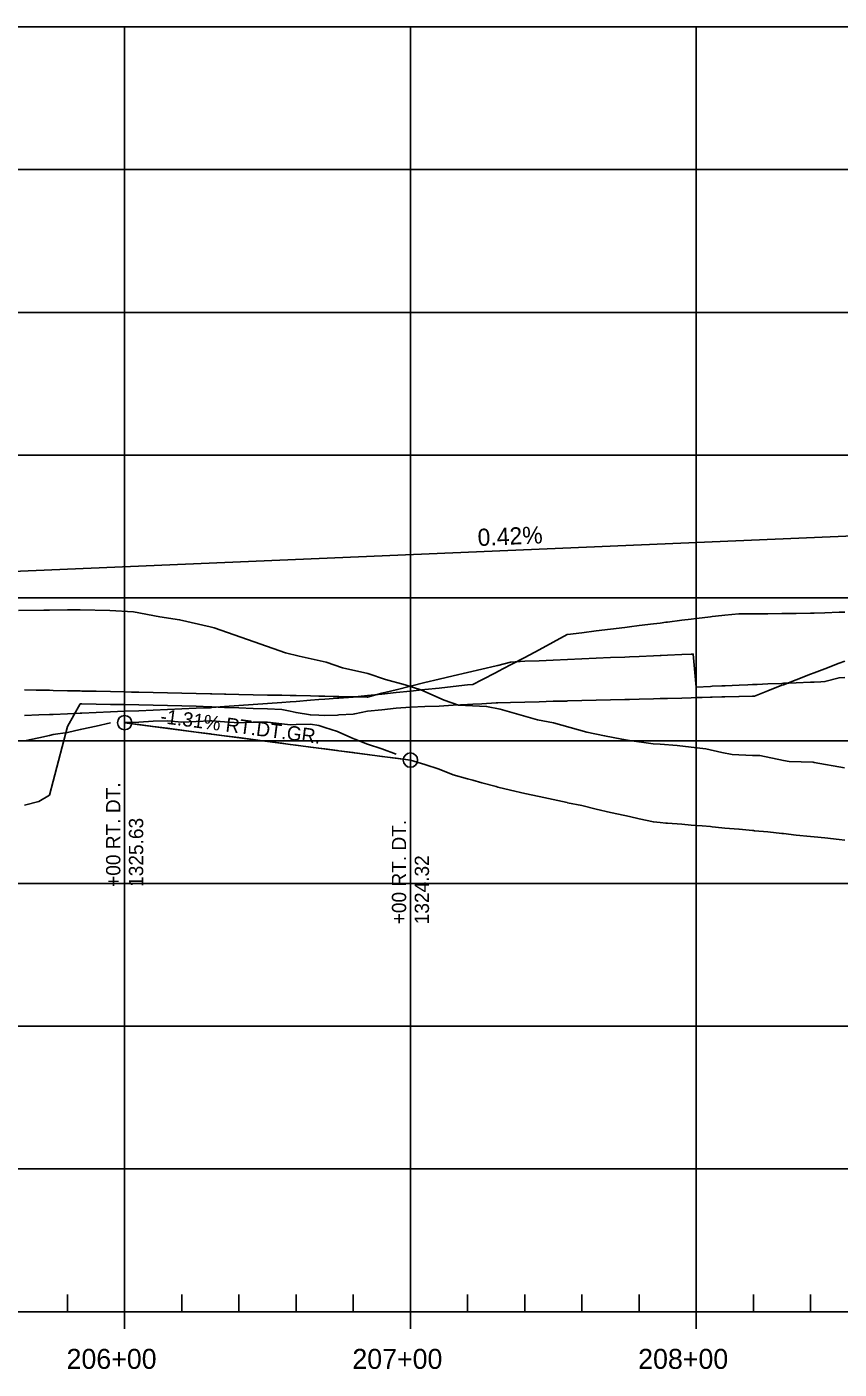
# Model space of a CAD drawing. Extents: x 1371206 to 1374178, y 379328 to 381511.
# Drawn here: x 1371810.4 to 1372094.6, y 379328.3 to 379798.4 of the extents above; entities that cross this region are included whole.
import ezdxf

# ---------------------------------------------------------------- set-up
doc = ezdxf.new("R2010")
doc.units = 0
for name, color, linetype in [('30', 7, 'Continuous'), ('37', 7, 'Continuous'), ('R_Exist Surface', 7, 'Continuous'), ('R_Profile Work Left', 7, 'Continuous'), ('R_Profile Work Right', 7, 'Continuous'), ('R_Vert Alg', 7, 'Continuous'), ('R_Vert Alg Annot', 7, 'Continuous')]:
    doc.layers.add(name, color=color, linetype=linetype)

msp = doc.modelspace()

# ---------------------------------------------------------------- linework, layer by layer
at = {"layer": '37'}
for p, q in [((1371244.63, 379798.35), (1374144.63, 379798.35)), ((1371244.63, 379798.35), (1374144.63, 379798.35)), ((1371844.63, 379348.35), (1371844.63, 379798.35)), ((1371944.63, 379348.35), (1371944.63, 379798.35)), ((1372044.63, 379348.35), (1372044.63, 379798.35)), ((1371244.63, 379748.35), (1374144.63, 379748.35)), ((1371244.63, 379698.35), (1374144.63, 379698.35)), ((1371244.63, 379648.35), (1374144.63, 379648.35)), ((1371244.63, 379598.35), (1372944.63, 379598.35)), ((1371244.63, 379598.35), (1374144.63, 379598.35)), ((1371244.63, 379548.35), (1374144.63, 379548.35)), ((1371244.63, 379498.35), (1374144.63, 379498.35)), ((1371244.63, 379448.35), (1374144.63, 379448.35)), ((1371244.63, 379398.35), (1374144.63, 379398.35)), ((1371824.63, 379348.35), (1371824.63, 379354.35)), ((1371864.63, 379348.35), (1371864.63, 379354.35)), ((1371884.63, 379348.35), (1371884.63, 379354.35)), ((1371904.63, 379348.35), (1371904.63, 379354.35)), ((1371924.63, 379348.35), (1371924.63, 379354.35)), ((1371964.63, 379348.35), (1371964.63, 379354.35)), ((1371984.63, 379348.35), (1371984.63, 379354.35)), ((1372004.63, 379348.35), (1372004.63, 379354.35)), ((1372024.63, 379348.35), (1372024.63, 379354.35)), ((1372064.63, 379348.35), (1372064.63, 379354.35)), ((1372084.63, 379348.35), (1372084.63, 379354.35)), ((1371244.63, 379348.35), (1374144.63, 379348.35)), ((1371844.63, 379342.35), (1371844.63, 379348.35)), ((1371944.63, 379342.35), (1371944.63, 379348.35)), ((1372044.63, 379342.35), (1372044.63, 379348.35))]:
    msp.add_line(p, q, dxfattribs=at)
at = {"layer": 'R_Exist Surface'}
msp.add_lwpolyline([(1371807.48, 379593.89), (1371816.35, 379594.05), (1371817.82, 379594.06), (1371818.29, 379594.07), (1371824.63, 379594.19), (1371829.09, 379594.13), (1371839.44, 379593.98), (1371847.69, 379593.51), (1371856.98, 379591.72), (1371863.87, 379590.72), (1371874.53, 379588.2), (1371875.94, 379587.83), (1371889.92, 379582.95), (1371900.89, 379579.12), (1371905.73, 379577.97), (1371915.12, 379575.87), (1371920.81, 379573.92), (1371929.75, 379571.83), (1371935.91, 379569.74), (1371942.82, 379567.96), (1371948.22, 379566.14), (1371956.43, 379562.5), (1371961.5, 379560.78), (1371971.3, 379560.34), (1371976.01, 379559.4), (1371989.13, 379555.71), (1371994.67, 379554.59), (1372006.38, 379551.35), (1372012.59, 379550.09), (1372018.57, 379548.87), (1372021.26, 379548.47), (1372029.57, 379547.29), (1372032.03, 379547.1), (1372037.96, 379546.69), (1372042.81, 379546.07), (1372048.01, 379545.47), (1372053.58, 379544.27), (1372057.26, 379543.53), (1372064.36, 379543.2), (1372066.93, 379543.12), (1372075.13, 379541.47), (1372077.11, 379541.09), (1372085.53, 379540.82), (1372085.91, 379540.75), (1372096.5, 379538.79)], dxfattribs=at)
at = {"layer": 'R_Profile Work Left'}
for points in [[(1371809.63, 379566.18), (1371813.63, 379566.1), (1371814.63, 379566.07), (1371818.29, 379566), (1371819.63, 379565.97), (1371824.63, 379565.86), (1371829.09, 379565.76), (1371829.63, 379565.75), (1371834.63, 379565.64), (1371839.63, 379565.53), (1371844.63, 379565.43), (1371847.07, 379565.37), (1371849.63, 379565.32), (1371854.63, 379565.21), (1371859.63, 379565.1), (1371864.63, 379564.99), (1371869.63, 379564.89), (1371874.63, 379564.78), (1371875.18, 379564.77), (1371879.63, 379564.67), (1371880.05, 379564.66), (1371884.63, 379564.56), (1371889.63, 379564.45), (1371894.63, 379564.35), (1371899.63, 379564.24), (1371902.52, 379564.18), (1371904.63, 379564.13), (1371909.63, 379564.02), (1371912.63, 379563.96), (1371913.63, 379563.94), (1371914.63, 379563.91), (1371917.71, 379563.85), (1371919.11, 379563.82), (1371919.63, 379563.81), (1371924.63, 379563.7), (1371925.17, 379563.69), (1371925.18, 379563.69), (1371929.49, 379563.61), (1371929.63, 379563.65), (1371934.63, 379564.95), (1371939.63, 379566.22), (1371944.63, 379567.48), (1371949.63, 379568.71), (1371954.63, 379569.92), (1371959.63, 379571.11), (1371964.63, 379572.27), (1371969.63, 379573.42), (1371974.63, 379574.54), (1371975.17, 379574.66), (1371979.63, 379575.88), (1371984.63, 379576.16), (1371989.63, 379576.37), (1371994.63, 379576.58), (1371999.63, 379576.79), (1372004.63, 379577.01), (1372009.63, 379577.22), (1372014.63, 379577.43), (1372019.63, 379577.64), (1372021.26, 379577.71), (1372024.63, 379577.85), (1372029.63, 379578.07), (1372032.03, 379578.17), (1372032.04, 379578.17), (1372032.42, 379578.18), (1372034.63, 379578.28), (1372039.63, 379578.49), (1372042.81, 379578.62), (1372042.82, 379578.62), (1372043.58, 379578.66), (1372044.63, 379567.15), (1372049.63, 379567.36), (1372050.18, 379567.39), (1372053.58, 379567.53), (1372053.6, 379567.53), (1372054.63, 379567.58), (1372054.74, 379567.58), (1372059.63, 379567.79), (1372062.69, 379567.92), (1372064.36, 379567.99), (1372064.38, 379567.99), (1372064.63, 379568), (1372065.9, 379568.05), (1372069.63, 379568.21), (1372074.63, 379568.42), (1372075.13, 379568.44), (1372075.16, 379568.45), (1372077.06, 379568.53), (1372079.63, 379568.64), (1372084.63, 379568.85), (1372085.91, 379568.9), (1372085.94, 379568.9), (1372088.22, 379569), (1372089.63, 379569.06), (1372094.63, 379570.4), (1372096.68, 379570.49)], [(1371829.09, 379561.24), (1371829.63, 379561.22), (1371834.63, 379561.11), (1371839.63, 379561.05), (1371844.63, 379560.99), (1371849.63, 379560.93), (1371854.63, 379560.8), (1371859.63, 379560.66), (1371864.63, 379560.53), (1371869.63, 379560.39), (1371874.63, 379560.23), (1371875.18, 379560.21), (1371879.63, 379560.03), (1371884.63, 379559.83), (1371889.63, 379559.62), (1371894.63, 379559.49), (1371899.63, 379559.24), (1371902.52, 379558.67), (1371904.63, 379558.22), (1371909.63, 379557.35), (1371912.63, 379557.25), (1371914.63, 379557.19), (1371919.11, 379557.34), (1371919.63, 379557.35), (1371924.63, 379557.66), (1371925.17, 379557.76), (1371925.18, 379557.76), (1371929.63, 379558.66), (1371934.63, 379559.18), (1371939.63, 379559.71), (1371944.63, 379560.05), (1371949.63, 379560.27), (1371954.63, 379560.49), (1371959.63, 379560.82), (1371964.63, 379561.03), (1371966.49, 379561.13), (1371969.63, 379561.3), (1371974.63, 379561.57), (1371975.17, 379561.6), (1371979.63, 379561.78), (1371984.63, 379561.88), (1371989.63, 379562.01), (1371994.63, 379562.14), (1371999.49, 379562.25), (1371999.63, 379562.26), (1372004.63, 379562.37), (1372009.63, 379562.5), (1372014.63, 379562.62), (1372019.63, 379562.75), (1372021.26, 379562.79), (1372024.63, 379562.88), (1372029.63, 379563.02), (1372032.03, 379563.08), (1372034, 379563.13), (1372034.63, 379563.15), (1372039.63, 379563.29), (1372042.81, 379563.37), (1372044.63, 379563.43), (1372046.75, 379563.48), (1372049.63, 379563.57), (1372050.18, 379563.58), (1372053.58, 379563.68), (1372054.63, 379563.71), (1372059.49, 379563.79), (1372059.63, 379563.79), (1372064.36, 379563.89), (1372064.63, 379563.9), (1372065.04, 379563.91), (1372069.63, 379565.77), (1372074.63, 379567.78), (1372075.13, 379567.97), (1372079.63, 379569.71), (1372084.63, 379571.62), (1372085.91, 379572.1), (1372089.63, 379573.53), (1372094.63, 379575.45), (1372096.68, 379576.23)], [(1371809.63, 379525.74), (1371814.63, 379527.11), (1371818.29, 379529.28), (1371819.63, 379534.19), (1371824.63, 379553.31), (1371829.09, 379561.24)]]:
    msp.add_lwpolyline(points, dxfattribs=at)
at = {"layer": 'R_Profile Work Right'}
for points in [[(1371809.63, 379557.15), (1371814.63, 379557.37), (1371818.29, 379557.52), (1371819.63, 379557.58), (1371824.63, 379557.79), (1371829.09, 379557.98), (1371829.63, 379558), (1371834.63, 379558.22), (1371839.63, 379558.43), (1371844.63, 379558.64), (1371849.63, 379558.85), (1371854.63, 379559.06), (1371859.63, 379559.28), (1371864.63, 379559.49), (1371869.63, 379559.7), (1371874.63, 379559.91), (1371875.18, 379559.94), (1371879.63, 379560.27), (1371884.63, 379560.64), (1371889.63, 379561.01), (1371894.63, 379561.38), (1371899.63, 379561.76), (1371902.52, 379561.97), (1371904.63, 379562.13), (1371909.63, 379562.5), (1371912.63, 379562.72), (1371914.63, 379562.87), (1371919.11, 379563.21), (1371919.63, 379563.25), (1371924.63, 379563.62), (1371925.17, 379563.66), (1371925.18, 379563.66), (1371929.63, 379564.13), (1371934.63, 379564.67), (1371939.63, 379565.2), (1371944.63, 379565.73), (1371949.63, 379566.26), (1371954.63, 379566.79), (1371959.63, 379567.33), (1371964.63, 379567.86), (1371966.49, 379568.06), (1371969.63, 379569.67), (1371974.63, 379572.26), (1371975.17, 379572.54), (1371979.63, 379574.87), (1371984.63, 379577.52), (1371989.63, 379580.19), (1371994.63, 379582.88), (1371999.49, 379585.53), (1371999.63, 379585.54), (1372004.63, 379586.16), (1372009.63, 379586.78), (1372014.63, 379587.4), (1372019.63, 379588.03), (1372021.26, 379588.23), (1372024.63, 379588.65), (1372029.63, 379589.27), (1372032.03, 379589.56), (1372034, 379589.81), (1372034.63, 379589.89), (1372039.63, 379590.51), (1372042.81, 379590.9), (1372044.63, 379591.13), (1372046.75, 379591.39), (1372049.63, 379591.75), (1372050.18, 379591.81), (1372053.58, 379592.16), (1372054.63, 379592.27), (1372059.49, 379592.77), (1372059.63, 379592.77), (1372064.36, 379592.78), (1372064.63, 379592.78), (1372065.04, 379592.78), (1372069.63, 379592.81), (1372074.63, 379592.87), (1372075.13, 379592.88), (1372079.63, 379592.95), (1372084.63, 379593.05), (1372085.91, 379593.07), (1372089.63, 379593.17), (1372094.63, 379593.31), (1372096.68, 379593.37)], [(1371809.63, 379548.27), (1371814.63, 379549.37), (1371818.29, 379550.18), (1371819.63, 379550.48), (1371824.63, 379551.26), (1371829.09, 379552.25), (1371829.63, 379552.37), (1371834.63, 379553.49), (1371839.63, 379554.61)], [(1371844.63, 379554.67), (1371849.63, 379554.85), (1371854.63, 379555.15), (1371859.63, 379555.27), (1371864.63, 379554.85), (1371869.63, 379555.08), (1371874.63, 379555.3), (1371875.18, 379555.33), (1371879.63, 379554.98), (1371884.63, 379554.66), (1371889.63, 379554.81), (1371894.63, 379554.82), (1371899.63, 379554.26), (1371902.52, 379553.96), (1371904.63, 379554), (1371909.63, 379554.09), (1371912.63, 379553.69), (1371914.63, 379553.02), (1371919.11, 379551.52), (1371919.63, 379551.35), (1371924.63, 379549.12), (1371925.17, 379548.87), (1371925.18, 379548.86), (1371929.63, 379547.12), (1371934.63, 379545.5), (1371939.63, 379543.62)], [(1371844.63, 379554.65), (1371849.63, 379554), (1371854.63, 379553.34), (1371859.63, 379552.69), (1371864.63, 379552.03), (1371869.63, 379551.38), (1371874.63, 379550.72), (1371875.18, 379550.65), (1371879.63, 379550.07), (1371884.63, 379549.41), (1371889.63, 379548.76), (1371894.63, 379548.1), (1371899.63, 379547.45), (1371902.52, 379547.07), (1371904.63, 379546.79), (1371909.63, 379546.14), (1371912.63, 379545.74), (1371914.63, 379545.48), (1371919.11, 379544.89), (1371919.63, 379544.83), (1371924.63, 379544.17), (1371925.17, 379544.1), (1371925.18, 379544.1), (1371929.63, 379543.52), (1371934.63, 379542.86), (1371939.63, 379542.21)], [(1371939.63, 379542.21), (1371944.63, 379541.51), (1371949.63, 379539.97), (1371954.63, 379538.43), (1371959.63, 379536.43), (1371964.63, 379535.01), (1371966.49, 379534.49), (1371969.63, 379533.63), (1371974.63, 379532.26), (1371975.17, 379532.12), (1371979.63, 379531.06), (1371984.63, 379529.91), (1371989.63, 379528.84), (1371994.63, 379527.75), (1371999.49, 379526.67), (1371999.63, 379526.64), (1372004.63, 379525.61), (1372009.63, 379524.41), (1372014.63, 379523.22), (1372019.63, 379522.2), (1372021.26, 379521.81), (1372024.63, 379520.99), (1372029.63, 379519.89), (1372032.03, 379519.66), (1372034, 379519.5), (1372034.63, 379519.45), (1372039.63, 379519.06), (1372042.81, 379518.81), (1372044.63, 379518.67), (1372046.75, 379518.5), (1372049.63, 379518.27), (1372050.18, 379518.23), (1372053.58, 379517.89), (1372054.63, 379517.77), (1372059.49, 379517.32), (1372059.63, 379517.31), (1372064.36, 379516.87), (1372064.63, 379516.85), (1372065.04, 379516.81), (1372069.63, 379516.39), (1372074.63, 379515.85), (1372075.13, 379515.79), (1372079.63, 379515.26), (1372084.63, 379514.78), (1372085.91, 379514.66), (1372089.63, 379514.3), (1372094.63, 379513.78), (1372096.68, 379513.53)]]:
    msp.add_lwpolyline(points, dxfattribs=at)
at = {"layer": 'R_Vert Alg'}
for p, q in [((1371594.63, 379598.67), (1372369.63, 379631.53)), ((1371844.63, 379554.65), (1371944.63, 379541.55))]:
    msp.add_line(p, q, dxfattribs=at)
for centre in [(1371844.63, 379554.65), (1371944.63, 379541.55)]:
    msp.add_circle(centre, 2.5, dxfattribs=at)
at = {"layer": 'R_Vert Alg Annot'}
for p, q in [((1371844.63, 379554.65), (1371844.63, 379497.32)), ((1371944.63, 379541.55), (1371944.63, 379484))]:
    msp.add_line(p, q, dxfattribs=at)

# ---------------------------------------------------------------- texts
at = {"layer": '30'}
for s, p in [('206+00', (1371824.32, 379328.35)), ('207+00', (1371924.32, 379328.35)), ('208+00', (1372024.32, 379328.35))]:
    msp.add_text(s, height=7, dxfattribs=at).set_placement(p)
at = {"layer": 'R_Vert Alg Annot'}
for s, height, rotation, p in [('0.42%', 6, 2.4279, (1371968.26, 379616.52)), ('-1.31% RT.DT.GR.', 5, 352.5368, (1371856.9, 379554.56)), ('+00 RT. DT.', 5, 90, (1371843.13, 379497.15)), ('1325.63', 5, 90, (1371851.13, 379497.15)), ('+00 RT. DT.', 5, 90, (1371943.13, 379484.05)), ('1324.32', 5, 90, (1371951.13, 379484.05))]:
    msp.add_text(s, height=height, rotation=rotation, dxfattribs=at).set_placement(p)

doc.saveas('drawing.dxf')
